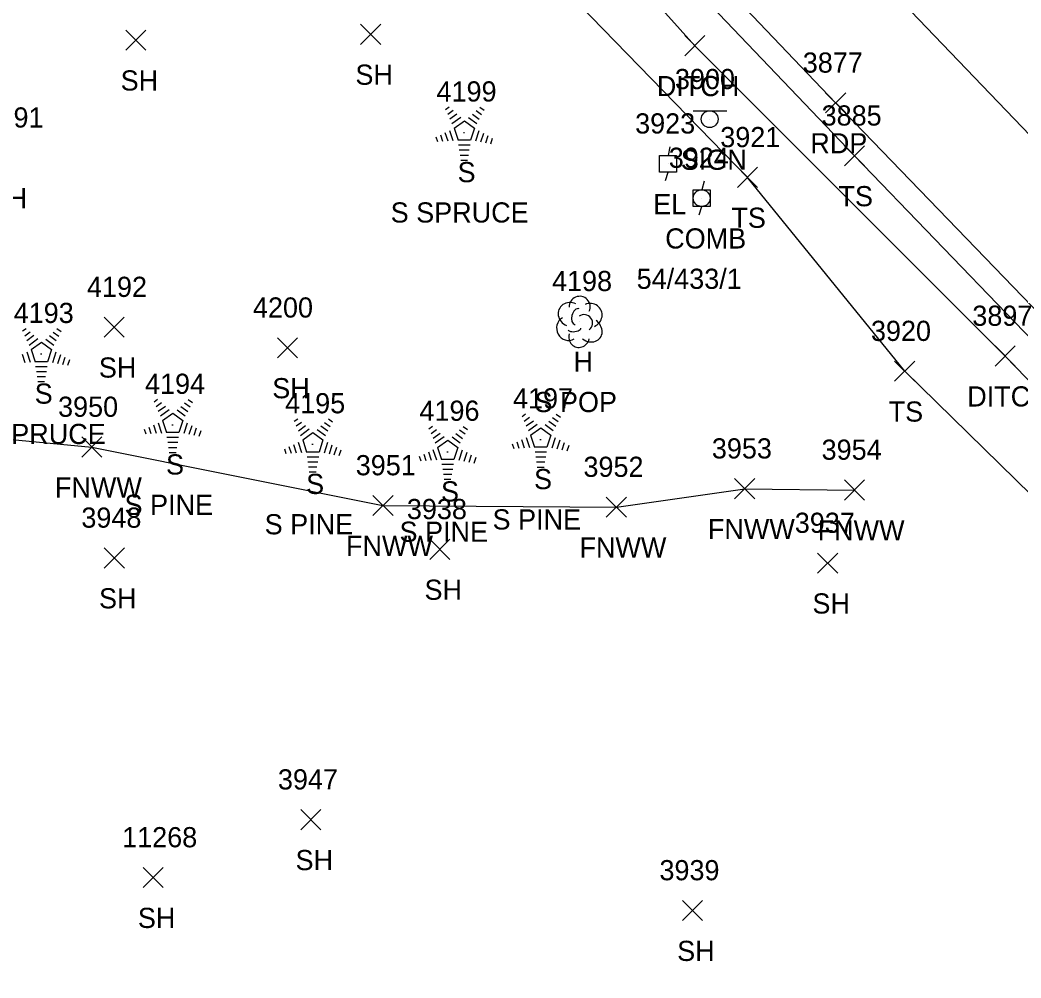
# Model space of a CAD drawing. Extents: x 1482574 to 1485769, y 580696 to 595649.
# Drawn here: x 1483701.6 to 1483800.8, y 583247.8 to 583342.7 of the extents above; entities that cross this region are included whole.
import ezdxf

# ---------------------------------------------------------------- set-up
doc = ezdxf.new("R2010")
doc.units = 0
for name, color, linetype in [('D_A', 7, 'Continuous'), ('D_I', 7, 'Continuous'), ('D_TIC', 7, 'Continuous'), ('DD', 7, 'Continuous'), ('L_A', 7, 'Continuous'), ('L_C', 7, 'Continuous'), ('L_I', 7, 'Continuous'), ('L_TIC', 7, 'Continuous'), ('LELB', 7, 'Continuous'), ('LFNC', 7, 'Continuous'), ('LTC', 7, 'Continuous'), ('LTD', 7, 'Continuous'), ('P_A', 7, 'Continuous'), ('P_I', 7, 'Continuous'), ('P_TIC', 7, 'Continuous'), ('PET', 7, 'Continuous'), ('PRC', 7, 'Continuous'), ('S_A', 7, 'Continuous'), ('S_I', 7, 'Continuous'), ('SSGN', 7, 'Continuous'), ('U_A', 7, 'Continuous'), ('U_C', 7, 'Continuous'), ('U_I', 7, 'Continuous'), ('UEPT', 7, 'Continuous'), ('UP', 7, 'Continuous')]:
    doc.layers.add(name, color=color, linetype=linetype)

msp = doc.modelspace()

# ---------------------------------------------------------------- linework, layer by layer
at = {"layer": 'D_TIC'}
for points in [[(1483767.46, 583339.185), (1483769.46, 583341.185)], [(1483769.46, 583339.185), (1483767.46, 583341.185)], [(1483798.217, 583308.417), (1483800.217, 583310.417)], [(1483800.217, 583308.417), (1483798.217, 583310.417)]]:
    msp.add_lwpolyline(points, dxfattribs=at)
at = {"layer": 'DD'}
msp.add_lwpolyline([(1483889.345, 583212.364), (1483861.514, 583244.404), (1483828.988, 583278.673), (1483799.217, 583309.417), (1483768.46, 583340.185), (1483754.529, 583355.756)], dxfattribs=at)
at = {"layer": 'L_TIC'}
for points in [[(1483712.076, 583339.743), (1483714.076, 583341.743)], [(1483714.076, 583339.743), (1483712.076, 583341.743)], [(1483735.34, 583340.314), (1483737.34, 583342.314)], [(1483737.34, 583340.314), (1483735.34, 583342.314)], [(1483783.283, 583328.27), (1483785.283, 583330.27)], [(1483785.283, 583328.27), (1483783.283, 583330.27)], [(1483772.673, 583326.131), (1483774.673, 583328.131)], [(1483774.673, 583326.131), (1483772.673, 583328.131)], [(1483709.917, 583311.282), (1483711.917, 583313.282)], [(1483711.917, 583311.282), (1483709.917, 583313.282)], [(1483727.099, 583309.234), (1483729.099, 583311.234)], [(1483729.099, 583309.234), (1483727.099, 583311.234)], [(1483788.257, 583306.918), (1483790.257, 583308.918)], [(1483790.257, 583306.918), (1483788.257, 583308.918)], [(1483707.709, 583299.395), (1483709.709, 583301.395)], [(1483709.709, 583299.395), (1483707.709, 583301.395)], [(1483772.407, 583295.265), (1483774.407, 583297.265)], [(1483774.407, 583295.265), (1483772.407, 583297.265)], [(1483783.283, 583295.137), (1483785.283, 583297.137)], [(1483785.283, 583295.137), (1483783.283, 583297.137)], [(1483736.554, 583293.598), (1483738.554, 583295.598)], [(1483738.554, 583293.598), (1483736.554, 583295.598)], [(1483759.684, 583293.44), (1483761.684, 583295.44)], [(1483761.684, 583293.44), (1483759.684, 583295.44)], [(1483742.187, 583289.251), (1483744.187, 583291.251)], [(1483744.187, 583289.251), (1483742.187, 583291.251)], [(1483709.933, 583288.401), (1483711.933, 583290.401)], [(1483711.933, 583288.401), (1483709.933, 583290.401)], [(1483780.626, 583287.889), (1483782.626, 583289.889)], [(1483782.626, 583287.889), (1483780.626, 583289.889)], [(1483729.409, 583262.45), (1483731.409, 583264.45)], [(1483731.409, 583262.45), (1483729.409, 583264.45)], [(1483713.784, 583256.717), (1483715.784, 583258.717)], [(1483715.784, 583256.717), (1483713.784, 583258.717)], [(1483767.223, 583253.447), (1483769.223, 583255.447)], [(1483769.223, 583253.447), (1483767.223, 583255.447)]]:
    msp.add_lwpolyline(points, dxfattribs=at)
at = {"layer": 'LELB'}
for points in [[(1484007.987, 583094.451), (1483976.241, 583127.275), (1483941.146, 583164.214), (1483912.308, 583195.389), (1483879.28, 583229.965), (1483847.954, 583263.095), (1483816.12, 583296.232), (1483784.283, 583329.27), (1483758.86, 583355.953)], [(1483855.277, 583169.362), (1483860.667, 583182.78), (1483870.533, 583196.439), (1483877.577, 583203.079), (1483878.896, 583210.175), (1483866.202, 583230.707), (1483836.097, 583260.156), (1483811.248, 583286.412), (1483789.257, 583307.918), (1483773.673, 583327.131), (1483749.828, 583351.668)]]:
    msp.add_lwpolyline(points, dxfattribs=at)
at = {"layer": 'LFNC'}
msp.add_lwpolyline([(1483690.035, 583302.167), (1483708.709, 583300.395), (1483737.554, 583294.598), (1483760.684, 583294.44), (1483773.407, 583296.265), (1483784.283, 583296.137)], dxfattribs=at)
at = {"layer": 'LTC'}
for p, q in [((1483743.761, 583333.863), (1483744.116, 583334.121)), ((1483743.971, 583333.398), (1483744.5, 583333.782)), ((1483746.788, 583333.755), (1483747.338, 583333.356)), ((1483747.159, 583334.104), (1483747.579, 583333.799)), ((1483744.18, 583332.932), (1483744.884, 583333.443)), ((1483744.39, 583332.466), (1483745.268, 583333.104)), ((1483744.615, 583332.011), (1483745.626, 583332.746)), ((1483745.626, 583332.746), (1483746.623, 583332.021)), ((1483746.046, 583333.059), (1483746.856, 583332.47)), ((1483746.417, 583333.407), (1483747.097, 583332.913)), ((1483743.705, 583331.576), (1483743.976, 583330.74)), ((1483744.16, 583331.792), (1483744.491, 583330.773)), ((1483744.615, 583332.011), (1483745.002, 583330.818)), ((1483746.623, 583332.021), (1483746.232, 583330.818)), ((1483747.061, 583331.75), (1483746.723, 583330.71)), ((1483742.794, 583331.142), (1483742.946, 583330.674)), ((1483743.249, 583331.359), (1483743.461, 583330.707)), ((1483746.232, 583330.818), (1483745.002, 583330.818)), ((1483747.505, 583331.499), (1483747.218, 583330.615)), ((1483747.95, 583331.249), (1483747.713, 583330.52)), ((1483748.394, 583330.999), (1483748.207, 583330.425)), ((1483746.194, 583330.318), (1483745.049, 583330.318)), ((1483746.11, 583329.818), (1483745.122, 583329.818)), ((1483746.026, 583329.318), (1483745.195, 583329.318)), ((1483745.942, 583328.818), (1483745.267, 583328.818)), ((1483701.855, 583311.904), (1483702.21, 583312.162)), ((1483702.065, 583311.439), (1483702.594, 583311.823)), ((1483704.882, 583311.796), (1483705.432, 583311.397)), ((1483705.253, 583312.145), (1483705.673, 583311.84)), ((1483702.274, 583310.973), (1483702.978, 583311.484)), ((1483702.484, 583310.507), (1483703.362, 583311.145)), ((1483702.709, 583310.052), (1483703.72, 583310.787)), ((1483703.72, 583310.787), (1483704.717, 583310.062)), ((1483704.14, 583311.1), (1483704.95, 583310.511)), ((1483704.511, 583311.448), (1483705.191, 583310.954)), ((1483702.254, 583309.833), (1483702.585, 583308.814)), ((1483702.709, 583310.052), (1483703.096, 583308.859)), ((1483704.717, 583310.062), (1483704.326, 583308.859)), ((1483705.155, 583309.791), (1483704.817, 583308.751)), ((1483701.799, 583309.617), (1483702.07, 583308.781)), ((1483704.326, 583308.859), (1483703.096, 583308.859)), ((1483705.599, 583309.54), (1483705.312, 583308.656)), ((1483706.044, 583309.29), (1483705.807, 583308.561)), ((1483706.488, 583309.04), (1483706.301, 583308.466)), ((1483704.288, 583308.359), (1483703.143, 583308.359)), ((1483704.204, 583307.859), (1483703.216, 583307.859)), ((1483704.12, 583307.359), (1483703.289, 583307.359)), ((1483704.036, 583306.859), (1483703.361, 583306.859)), ((1483714.87, 583304.88), (1483715.225, 583305.138)), ((1483715.08, 583304.415), (1483715.609, 583304.799)), ((1483717.897, 583304.772), (1483718.447, 583304.373)), ((1483718.268, 583305.121), (1483718.688, 583304.816)), ((1483715.289, 583303.949), (1483715.993, 583304.46)), ((1483715.499, 583303.483), (1483716.377, 583304.121)), ((1483717.155, 583304.076), (1483717.965, 583303.487)), ((1483717.526, 583304.424), (1483718.206, 583303.93)), ((1483715.269, 583302.809), (1483715.6, 583301.79)), ((1483715.724, 583303.028), (1483716.735, 583303.763)), ((1483715.724, 583303.028), (1483716.111, 583301.835)), ((1483716.735, 583303.763), (1483717.732, 583303.038)), ((1483717.732, 583303.038), (1483717.341, 583301.835)), ((1483728.754, 583302.951), (1483729.109, 583303.209)), ((1483728.964, 583302.486), (1483729.493, 583302.87)), ((1483731.781, 583302.843), (1483732.331, 583302.444)), ((1483732.152, 583303.192), (1483732.572, 583302.887)), ((1483751.336, 583303.43), (1483751.691, 583303.688)), ((1483751.546, 583302.965), (1483752.075, 583303.349)), ((1483751.755, 583302.499), (1483752.459, 583303.01)), ((1483753.992, 583302.974), (1483754.672, 583302.48)), ((1483754.363, 583303.322), (1483754.913, 583302.923)), ((1483754.734, 583303.671), (1483755.154, 583303.366)), ((1483713.903, 583302.159), (1483714.055, 583301.691)), ((1483714.358, 583302.376), (1483714.57, 583301.724)), ((1483714.814, 583302.593), (1483715.085, 583301.757)), ((1483717.341, 583301.835), (1483716.111, 583301.835)), ((1483718.17, 583302.767), (1483717.832, 583301.727)), ((1483718.614, 583302.516), (1483718.327, 583301.632)), ((1483719.059, 583302.266), (1483718.822, 583301.537)), ((1483719.503, 583302.016), (1483719.316, 583301.442)), ((1483729.173, 583302.02), (1483729.877, 583302.531)), ((1483729.383, 583301.554), (1483730.261, 583302.192)), ((1483729.608, 583301.099), (1483730.619, 583301.834)), ((1483730.619, 583301.834), (1483731.616, 583301.109)), ((1483731.039, 583302.147), (1483731.849, 583301.558)), ((1483731.41, 583302.495), (1483732.09, 583302.001)), ((1483742.117, 583302.209), (1483742.472, 583302.467)), ((1483742.327, 583301.744), (1483742.856, 583302.128)), ((1483742.536, 583301.278), (1483743.24, 583301.789)), ((1483745.144, 583302.101), (1483745.694, 583301.702)), ((1483745.515, 583302.45), (1483745.935, 583302.145)), ((1483751.965, 583302.033), (1483752.843, 583302.671)), ((1483752.19, 583301.578), (1483753.201, 583302.313)), ((1483753.201, 583302.313), (1483754.198, 583301.588)), ((1483753.621, 583302.626), (1483754.431, 583302.037)), ((1483717.303, 583301.335), (1483716.158, 583301.335)), ((1483717.219, 583300.835), (1483716.231, 583300.835)), ((1483729.153, 583300.88), (1483729.484, 583299.861)), ((1483729.608, 583301.099), (1483729.995, 583299.906)), ((1483731.616, 583301.109), (1483731.225, 583299.906)), ((1483732.054, 583300.838), (1483731.716, 583299.798)), ((1483742.746, 583300.812), (1483743.624, 583301.45)), ((1483742.971, 583300.357), (1483743.982, 583301.092)), ((1483743.982, 583301.092), (1483744.979, 583300.367)), ((1483744.402, 583301.405), (1483745.212, 583300.816)), ((1483744.773, 583301.753), (1483745.453, 583301.259)), ((1483750.824, 583300.926), (1483751.036, 583300.274)), ((1483751.28, 583301.143), (1483751.551, 583300.307)), ((1483751.735, 583301.359), (1483752.066, 583300.34)), ((1483752.19, 583301.578), (1483752.577, 583300.385)), ((1483754.198, 583301.588), (1483753.807, 583300.385)), ((1483754.636, 583301.317), (1483754.298, 583300.277)), ((1483755.08, 583301.066), (1483754.793, 583300.182)), ((1483755.525, 583300.816), (1483755.288, 583300.087)), ((1483717.135, 583300.335), (1483716.304, 583300.335)), ((1483717.051, 583299.835), (1483716.376, 583299.835)), ((1483727.787, 583300.23), (1483727.939, 583299.762)), ((1483728.242, 583300.447), (1483728.454, 583299.795)), ((1483728.698, 583300.664), (1483728.969, 583299.828)), ((1483731.225, 583299.906), (1483729.995, 583299.906)), ((1483732.498, 583300.587), (1483732.211, 583299.703)), ((1483732.943, 583300.337), (1483732.706, 583299.608)), ((1483733.387, 583300.087), (1483733.2, 583299.513)), ((1483742.061, 583299.922), (1483742.332, 583299.086)), ((1483742.516, 583300.138), (1483742.847, 583299.119)), ((1483742.971, 583300.357), (1483743.358, 583299.164)), ((1483744.979, 583300.367), (1483744.588, 583299.164)), ((1483745.417, 583300.096), (1483745.079, 583299.056)), ((1483745.861, 583299.845), (1483745.574, 583298.961)), ((1483750.369, 583300.709), (1483750.521, 583300.241)), ((1483753.807, 583300.385), (1483752.577, 583300.385)), ((1483753.769, 583299.885), (1483752.624, 583299.885)), ((1483755.969, 583300.566), (1483755.782, 583299.992)), ((1483731.187, 583299.406), (1483730.042, 583299.406)), ((1483731.103, 583298.906), (1483730.115, 583298.906)), ((1483741.15, 583299.488), (1483741.302, 583299.02)), ((1483741.605, 583299.705), (1483741.817, 583299.053)), ((1483744.588, 583299.164), (1483743.358, 583299.164)), ((1483746.306, 583299.595), (1483746.069, 583298.866)), ((1483746.75, 583299.345), (1483746.563, 583298.771)), ((1483753.685, 583299.385), (1483752.697, 583299.385)), ((1483753.601, 583298.885), (1483752.77, 583298.885)), ((1483731.019, 583298.406), (1483730.188, 583298.406)), ((1483730.935, 583297.906), (1483730.26, 583297.906)), ((1483744.55, 583298.664), (1483743.405, 583298.664)), ((1483744.466, 583298.164), (1483743.478, 583298.164)), ((1483753.517, 583298.385), (1483752.842, 583298.385)), ((1483744.382, 583297.664), (1483743.551, 583297.664)), ((1483744.298, 583297.164), (1483743.623, 583297.164))]:
    msp.add_line(p, q, dxfattribs=at)
at = {"layer": 'LTD'}
msp.add_line((1483757.003, 583312.862), (1483757.003, 583312.862), dxfattribs=at)
msp.add_line((1483757.003, 583312.862), (1483757.003, 583312.862), dxfattribs=at)
msp.add_arc((1483757.05, 583314.296), 1.047, 335.52715, 180.95627, dxfattribs=at)
for centre, major_axis, ratio, start_param, end_param in [((1483756.211, 583313.529), (1.21, -0.512), 0.895232, 1.570796, 4.712389), ((1483758.045, 583313.446), (-1.141, -0.483), 0.949671, 1.570796, 4.712389), ((1483756.795, 583313.32), (-0.208, -0.792), 0.645439, 3.141593, 6.283185), ((1483755.92, 583312.153), (0.584, -1.042), 0.959034, 3.141593, 6.283185), ((1483757.503, 583312.695), (-0.5, 0.667), 0.989748, 3.141593, 6.283185), ((1483758.003, 583312.029), (-1.09, 0.792), 0.841452, 1.570796, 4.712389), ((1483756.545, 583312.112), (-0.625, -0.083), 0.423636, 0, 3.141593), ((1483757.003, 583311.362), (0.265, 1.061), 0.942809, 1.570796, 4.712389)]:
    msp.add_ellipse(centre, major_axis=major_axis, ratio=ratio, start_param=start_param, end_param=end_param, dxfattribs=at)
at = {"layer": 'P_TIC'}
for points in [[(1483781.416, 583333.516), (1483783.416, 583335.516)], [(1483783.416, 583333.516), (1483781.416, 583335.516)]]:
    msp.add_lwpolyline(points, dxfattribs=at)
at = {"layer": 'PET'}
for points in [[(1483734.473, 583384.831), (1483782.416, 583334.516)], [(1483995.677, 583110.556), (1483966.609, 583141.15), (1483938.541, 583170.74), (1483909.414, 583201.245), (1483877.767, 583234.424), (1483846.425, 583267.587), (1483814.824, 583300.92), (1483782.416, 583334.516)]]:
    msp.add_lwpolyline(points, dxfattribs=at)
at = {"layer": 'PRC'}
msp.add_lwpolyline([(1484022.304, 583100.035), (1483990.861, 583133.204), (1483962.862, 583162.554), (1483929.316, 583197.8), (1483898.21, 583230.471), (1483864.906, 583265.08), (1483836.799, 583294.404), (1483804.05, 583328.833), (1483747.315, 583388.01), (1483714.346, 583422.232), (1483688.919, 583448.426), (1483665.487, 583472.786), (1483644.716, 583494.273)], dxfattribs=at)
at = {"layer": 'SSGN'}
for p, q in [((1483768.286, 583333.736), (1483771.619, 583333.736)), ((1483769.933, 583332.902), (1483769.933, 583332.902))]:
    msp.add_line(p, q, dxfattribs=at)
msp.add_circle((1483769.933, 583332.902), 0.833, dxfattribs=at)
at = {"layer": 'UEPT'}
for p, q in [((1483765.972, 583330.149), (1483765.805, 583329.315)), ((1483764.972, 583327.649), (1483764.972, 583329.315)), ((1483764.972, 583329.315), (1483766.638, 583329.315)), ((1483766.638, 583329.315), (1483766.638, 583327.649)), ((1483766.638, 583327.649), (1483764.972, 583327.649)), ((1483765.555, 583326.815), (1483765.805, 583327.649)), ((1483765.805, 583328.482), (1483765.805, 583328.482))]:
    msp.add_line(p, q, dxfattribs=at)
at = {"layer": 'UP'}
for p, q in [((1483769.389, 583326.747), (1483769.139, 583325.913)), ((1483768.306, 583324.247), (1483768.306, 583325.913)), ((1483768.306, 583325.913), (1483769.972, 583325.913)), ((1483769.972, 583325.913), (1483769.972, 583324.247)), ((1483769.139, 583325.08), (1483769.139, 583325.08)), ((1483769.972, 583324.247), (1483768.306, 583324.247)), ((1483768.889, 583323.413), (1483769.139, 583324.247))]:
    msp.add_line(p, q, dxfattribs=at)
msp.add_circle((1483769.139, 583325.08), 0.833, dxfattribs=at)

# ---------------------------------------------------------------- texts
at = {"layer": 'D_A'}
for p in [(1483764.696, 583335.185), (1483795.453, 583304.417)]:
    msp.add_text('DITCH', height=2, dxfattribs=at).set_placement(p)
at = {"layer": 'D_I'}
msp.add_text('3897', height=2, dxfattribs=at).set_placement((1483795.957, 583312.417))
at = {"layer": 'L_A'}
for s, p in [('SH', (1483711.564, 583335.743)), ('SH', (1483734.828, 583336.314)), ('S', (1483744.952, 583326.655)), ('SH', (1483698.588, 583324.073)), ('TS', (1483782.692, 583324.27)), ('TS', (1483772.082, 583322.131)), ('H', (1483756.436, 583307.862)), ('SH', (1483709.405, 583307.282)), ('SH', (1483726.587, 583305.234)), ('S', (1483703.046, 583304.696)), ('TS', (1483787.666, 583302.918)), ('S', (1483716.061, 583297.672)), ('S', (1483752.527, 583296.222)), ('FNWW', (1483705.055, 583295.395)), ('S', (1483729.945, 583295.743)), ('S', (1483743.308, 583295.001)), ('FNWW', (1483769.753, 583291.265)), ('FNWW', (1483780.629, 583291.137)), ('FNWW', (1483733.9, 583289.598)), ('FNWW', (1483757.03, 583289.44)), ('SH', (1483741.675, 583285.251)), ('SH', (1483709.421, 583284.401)), ('SH', (1483780.114, 583283.889)), ('SH', (1483728.897, 583258.45)), ('SH', (1483713.272, 583252.717)), ('SH', (1483766.711, 583249.447))]:
    msp.add_text(s, height=2, dxfattribs=at).set_placement(p)
at = {"layer": 'L_C'}
for s, p in [('S SPRUCE', (1483738.322, 583322.655)), ('S POP', (1483752.57, 583303.862)), ('S SPRUCE', (1483696.416, 583300.696)), ('S PINE', (1483711.951, 583293.672)), ('S PINE', (1483748.417, 583292.222)), ('S PINE', (1483725.835, 583291.743)), ('S PINE', (1483739.198, 583291.001))]:
    msp.add_text(s, height=2, dxfattribs=at).set_placement(p)
at = {"layer": 'L_I'}
for s, p in [('4199', (1483742.865, 583334.655)), ('4191', (1483697.974, 583332.073)), ('3885', (1483781.023, 583332.27)), ('3921', (1483770.98, 583330.131)), ('4198', (1483754.31, 583315.862)), ('4192', (1483708.224, 583315.282)), ('4193', (1483700.967, 583312.696)), ('4200', (1483724.674, 583313.234)), ('3920', (1483785.911, 583310.918)), ('4194', (1483713.982, 583305.672)), ('4195', (1483727.866, 583303.743)), ('4197', (1483750.448, 583304.222)), ('3950', (1483705.363, 583303.395)), ('4196', (1483741.174, 583303.001)), ('3953', (1483770.147, 583299.265)), ('3954', (1483781.023, 583299.137)), ('3951', (1483734.861, 583297.598)), ('3952', (1483757.424, 583297.44)), ('3938', (1483739.927, 583293.251)), ('3948', (1483707.673, 583292.401)), ('3937', (1483778.366, 583291.889)), ('3947', (1483727.149, 583266.45)), ('11268', (1483711.713, 583260.717)), ('3939', (1483764.955, 583257.447))]:
    msp.add_text(s, height=2, dxfattribs=at).set_placement(p)
at = {"layer": 'LTC'}
for p in [(1483745.509, 583331.759), (1483703.603, 583309.8), (1483716.618, 583302.776), (1483753.084, 583301.326), (1483730.502, 583300.847), (1483743.865, 583300.105)]:
    msp.add_text('.', height=1.037, rotation=270, dxfattribs=at).set_placement(p)
at = {"layer": 'P_A'}
msp.add_text('RDP', height=2, dxfattribs=at).set_placement((1483779.904, 583329.516))
at = {"layer": 'P_I'}
msp.add_text('3877', height=2, dxfattribs=at).set_placement((1483779.156, 583337.516))
at = {"layer": 'S_A'}
msp.add_text('SIGN', height=2, dxfattribs=at).set_placement((1483767.07, 583327.882))
at = {"layer": 'S_I'}
msp.add_text('3900', height=2, dxfattribs=at).set_placement((1483766.488, 583335.882))
at = {"layer": 'U_A'}
for s, p in [('EL', (1483764.34, 583323.482)), ('COMB', (1483765.525, 583320.08))]:
    msp.add_text(s, height=2, dxfattribs=at).set_placement(p)
at = {"layer": 'U_C'}
msp.add_text('54/433/1', height=2, dxfattribs=at).set_placement((1483762.698, 583316.08))
at = {"layer": 'U_I'}
for s, p in [('3923', (1483762.545, 583331.482)), ('3924', (1483765.879, 583328.08))]:
    msp.add_text(s, height=2, dxfattribs=at).set_placement(p)

doc.saveas('drawing.dxf')
